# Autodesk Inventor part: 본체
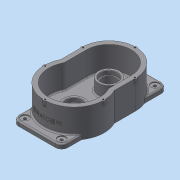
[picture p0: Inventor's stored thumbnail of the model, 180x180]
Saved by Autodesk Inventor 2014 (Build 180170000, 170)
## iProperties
Created: 2025-09
Part Number: 본체
Material: 일반
Document SubType Name: Modeling
Designer: dg
Density: 1 g/cm^3
Appearance: 기본값
Author: dg
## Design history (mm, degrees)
sketch "스케치1"
  geometry: L1 (-60, 0)-(-60, -48.184); L2 (60, 0)-(60, -48.184); A1 r 60 centre (0, 0) between (60, 0) and (-60, 0); A2 r 67 centre (0, -78) between (-60, -48.184) and (60, -48.184); 1 further point
  constraints: 4 end point, 4 point on circle, 2 centre point, 2 tangent, 1 coincident, 1 parallel, 1 vertical, 1 vertical alignment
  dimensions: "d0" = 120 diameter of A1; "d2" = 78 distance of point (0, 0) A2.centre; "d3" = 67 radius of A2
extrude "돌출1" new body sketch "스케치1" distance "d4" = 64; taper "d5" = 0 deg
feature "쉘1" dims "d6" = 10
sketch "스케치2"
  geometry: L1 (-55, 76)-(55, 76); L2 (55, 76)-(55, -161); L3 (55, -161)-(-55, -161); L4 (-55, -161)-(-55, 76); A1 r 60 centre (0, 0) between (60, 0) and (-60, 0) reference; 1 further point
  constraints: 8 end point, 2 parallel, 1 horizontal, 1 midpoint, 1 perpendicular, 1 vertical alignment
  dimensions: "d7" = 110 distance of L2.end L3.end; "d8" = 76 distance from line of L1 A1.centre; "d9" = 237 distance between parallel lines of L3 L1
extrude "돌출2" join sketch "스케치2" distance "d10" = 10; taper "d11" = 0 deg
sketch "스케치3"
  geometry: C1 r 23.5 at (0, 78); C2 r 23.5 at (0, 0); A1 r 57 centre (0, 0) between (-50, 27.368) and (50, 27.368) reference; A2 r 50 centre (0, 78) between (50, 78) and (-50, 78) reference
  constraints: 2 centre point, 2 coincident
  dimensions: "d12" = 47 diameter of C1; "d13" = 47 diameter of C2
extrude "돌출3" join sketch "스케치3" distance "d14" = 26; taper "d15" = 0 deg
extrude "돌출4" join sketch "스케치3" distance "d16" = 12; taper "d17" = 0 deg
hole "구멍1" diameter "d20" = 32; stored, may be unused: countersink angle "d24" = 90 deg, drill point angle "d26" = 0 deg; dims "d21" = 6, "d22" = 37, "d23" = 9, "d25" = 16, "d27" = 10, "d28" = 10
hole "구멍2" diameter "d31" = 30; stored, may be unused: countersink angle "d35" = 90 deg, drill point angle "d37" = 118 deg; dims "d29" = 10, "d30" = 10, "d32" = 6, "d33" = 37, "d34" = 9, "d36" = 16
hole "구멍3" diameter "d40" = 35; stored, may be unused: countersink angle "d44" = 90 deg, drill point angle "d46" = 0 deg; dims "d41" = 6, "d42" = 4, "d43" = 2, "d45" = 8.3, "d58" = 10, "d59" = 10
hole "구멍4" diameter "d49" = 28; stored, may be unused: countersink angle "d53" = 90 deg, drill point angle "d55" = 0 deg; dims "d50" = 6, "d51" = 4, "d52" = 2, "d54" = 3, "d56" = 10, "d57" = 10
fillet "모깎기1" dims "d72" = 14, "d73" = 0.3, "d74" = 13
sketch "스케치8"
  geometry: L1 (-60, 0)-(-60, -48.184) reference; L2 (60, -48.184)-(60, 0) reference; L3 (58, 0)-(58, -48.657); L4 (-58, -48.657)-(-58, 0); C1 r 4 at (58, 0); C2 r 4 at (-65, -78); C3 r 4 at (0, 58); C4 r 4 at (-58, 0); C5 r 4 at (0, -143); C6 r 4 at (65, -78); A1 r 50 centre (0, 0) between (50, 0) and (-50, 0) reference; A2 r 57 centre (0, -78) between (-51.3, -53.154) and (51.3, -53.154) reference; A3 r 60 centre (0, 0) between (60, 0) and (-60, 0) reference; A4 r 67 centre (0, -78) between (-60, -48.184) and (60, -48.184) reference; A5 r 58 centre (0, 0) between (58, 0) and (-58, 0); A6 r 65 centre (0, -78) between (-58, -48.657) and (58, -48.657)
  constraints: 8 centre point, 5 point on circle, 4 end point, 1 coincident, 1 horizontal alignment, 13 other
  dimensions: "d101" = 2 radial gap between concentric circles of A3 A5; "d102" = 8 diameter of C1; "d103" = 8 diameter of C2; "d106" = 180 deg dimension on A1.centre C1.centre C4.centre; "d110" = 180 deg dimension on A2.centre C2.centre C6.centre
extrude "돌출6" join sketch "스케치8" distance "d112" = 12; taper "d113" = 0 deg
fillet "모깎기2" dims "d75" = 3
fillet "모깎기3" dims "d76" = 3
fillet "모깎기4" dims "d77" = 3
sketch "스케치5"
  geometry: L1 (-41, 73)-(41, 73) reference; L2 (52, 62)-(52, 35.567) reference; L3 (-52, 35.567)-(-52, 62) reference; A1 r 11 centre (-41, -147) between (-52, -147) and (-41, -158) reference; A2 r 11 centre (41, -147) between (41, -158) and (52, -147) reference; A3 r 11 centre (41, 62) between (52, 62) and (41, 73) reference; A4 r 11 centre (-41, 62) between (-41, 73) and (-52, 62) reference; A5 r 63 centre (0, 0) between (52, 35.567) and (-52, 35.567) reference; 1 further point
hole "구멍5" sketch "스케치5" at (-41, -147), (41, -147), (41, 62), (-41, 62) diameter "d78" = 6.6; stored, may be unused: countersink angle "d82" = 90 deg, drill point angle "d84" = 118 deg; dims "d79" = 6, "d80" = 18, "d81" = 2, "d83" = 3
chamfer "모따기1" distance "d92" = 0.8; stored, may be unused: second distance "d93" = 2, angle "d94" = 30 deg
chamfer "모따기2" distance "d95" = 1; stored, may be unused: second distance "d96" = 2, angle "d97" = 30 deg
node "작업 평면1"
sketch "스케치7"
  geometry: L1 (55.514, 0)-(-55.514, 0) reference; 3 further points
  constraints: 1 vertical alignment, 1 other
  dimensions: "d98" = 30 distance from line of L1 point (0, 30)
feature "엠보싱1" sketch "스케치7" dims "d0" = 120, "d2" = 78, "d3" = 67, "d99" = 0.5, "d100" = 0
sketch "스케치9"
  geometry: A1 r 4 centre (58, 0) between (60, -3.464) and (59.897, 3.522) reference; A2 r 4 centre (0, 58) between (3.522, 59.897) and (-3.522, 59.897) reference; A3 r 4 centre (-58, 0) between (-59.897, 3.522) and (-60, -3.464) reference; A4 r 4 centre (-65, -78) between (-66.908, -74.484) and (-66.908, -81.516) reference; A5 r 4 centre (0, -143) between (-3.516, -144.908) and (3.516, -144.908) reference; A6 r 4 centre (65, -78) between (66.908, -81.516) and (66.908, -74.484) reference
hole "구멍7" sketch "스케치9" at (0, 58), (-58, 0), (-65, -78), (0, -143), (65, -78), (58, 0) diameter "d114" = 3.242; stored, may be unused: countersink angle "d118" = 90 deg, drill point angle "d120" = 118 deg; dims "d115" = 8, "d116" = 4, "d117" = 2, "d119" = 10
fillet "모깎기5" dims "d121" = 3
node "솔리드1"
node "투영된 루프1"
